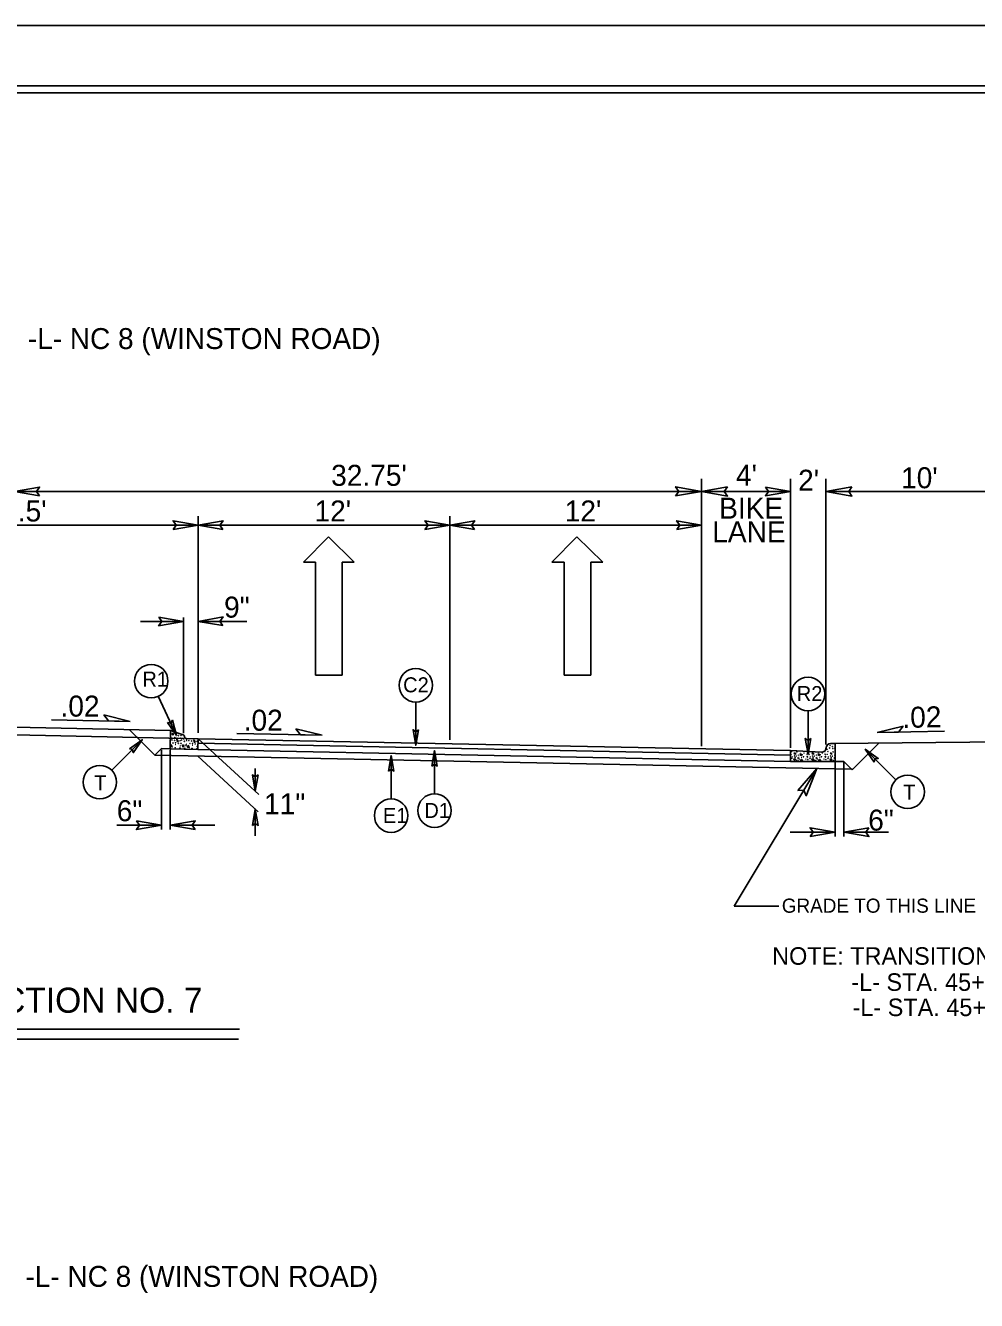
# Model space of a CAD drawing. Extents: x 957297 to 961629, y 830661 to 840840.
# Drawn here: x 959498.6 to 959851.8, y 836523.6 to 836997.1 of the extents above; entities that cross this region are included whole.
import ezdxf

# ---------------------------------------------------------------- set-up
doc = ezdxf.new("R2010")
doc.units = 0
for name, color, linetype in [('Default', 7, 'Continuous'), ('Old_Level_1', 7, 'Continuous'), ('Old_Level_11', 7, 'Continuous'), ('Old_Level_3', 7, 'Continuous'), ('Prop Dimension Text', 7, 'Continuous'), ('Prop Lane Arrow CELL', 7, 'Continuous'), ('Sheet Plot Border Inside CELL', 7, 'Continuous'), ('Sheet Plot Border Outside CELL', 7, 'Continuous'), ('Sheet Typical CELL', 7, 'Continuous'), ('Typical ID Circle CELL', 7, 'Continuous'), ('Typical Terminator CELL', 7, 'Continuous'), ('Typical Text ID Circle CELL', 7, 'Continuous')]:
    doc.layers.add(name, color=color, linetype=linetype)

# ---------------------------------------------------------------- blocks, each defined once
blk = doc.blocks.new('Lane Arrow Through')
at = {"layer": 'Prop Lane Arrow CELL'}
for p, q in [((-17.15, 1.6), (-3.15, 1.6)), ((-17.15, -1.7), (-17.15, 1.6)), ((-3.15, 1.6), (-3.15, 3.1)), ((-3.15, 3.1), (0, 0)), ((0, 0), (-3.15, -3.2)), ((-3.15, -1.7), (-17.15, -1.7)), ((-3.15, -3.2), (-3.15, -1.7))]:
    blk.add_line(p, q, dxfattribs=at)

msp = doc.modelspace()

# ---------------------------------------------------------------- linework, layer by layer
at = {"layer": 'Default'}
for p, q in [((959494.54, 836736.5), (959552.51, 836735.34)), ((959546.62, 836726.12), (959537.09, 836735.65)), ((959494.54, 836733.65), (959557.49, 836732.39))]:
    msp.add_line(p, q, dxfattribs=at)
at = {"layer": 'Old_Level_1'}
for p, q in [((959749.66, 836828.73), (959749.66, 836729.43)), ((959782.66, 836828.73), (959782.66, 836728.93)), ((959795.87, 836828.73), (959795.87, 836730.13)), ((959494.54, 836824.11), (959749.66, 836824.11)), ((959749.66, 836824.11), (959782.66, 836824.11)), ((959861.91, 836824.11), (959795.87, 836824.11)), ((959426.38, 836811.56), (959562.7, 836811.56)), ((959562.7, 836814.92), (959562.7, 836734.44)), ((959562.7, 836811.56), (959656.18, 836811.56)), ((959656.18, 836814.92), (959656.18, 836731.89)), ((959656.18, 836811.56), (959749.66, 836811.56)), ((959541.25, 836775.85), (959557.28, 836775.85)), ((959557.28, 836777.3), (959557.28, 836734.3)), ((959562.7, 836775.85), (959580.77, 836775.85)), ((959508.25, 836739.27), (959537.47, 836738.69)), ((959562.7, 836732.27), (959782.66, 836727.83)), ((959562.7, 836732.27), (959585.21, 836711.56)), ((959577.12, 836734.15), (959608.72, 836733.52)), ((959861.91, 836731.11), (959798.95, 836730.48)), ((959839.95, 836735.03), (959814.84, 836734.53)), ((959549.06, 836728.57), (959546.62, 836726.12)), ((959546.62, 836726.12), (959805.61, 836720.89)), ((959549.06, 836728.57), (959552.36, 836728.5)), ((959549.06, 836698.48), (959549.06, 836728.13)), ((959552.36, 836698.48), (959552.36, 836728.13)), ((959562.62, 836728.29), (959782.66, 836723.84)), ((959562.67, 836730.55), (959782.66, 836726.1)), ((959805.6, 836720.71), (959815.53, 836730.64)), ((959562.57, 836725.8), (959585.07, 836705.09)), ((959583.95, 836721.23), (959583.95, 836712.72)), ((959799.24, 836723.84), (959802.54, 836723.78)), ((959799.24, 836695.94), (959799.24, 836723.57)), ((959802.54, 836723.78), (959805.6, 836720.71)), ((959802.54, 836695.94), (959802.54, 836723.57)), ((959761.73, 836670.08), (959792.43, 836721.15)), ((959583.93, 836706.14), (959583.93, 836696.13)), ((959532.46, 836700.11), (959549.06, 836700.11)), ((959552.36, 836700.11), (959568.96, 836700.11)), ((959799.24, 836697.53), (959782.64, 836697.53)), ((959819.14, 836697.53), (959802.54, 836697.53)), ((959778.35, 836670.08), (959761.73, 836670.08)), ((959578.04, 836624.44), (959410.34, 836624.44)), ((959577.76, 836620.63), (959410.06, 836620.63))]:
    msp.add_line(p, q, dxfattribs=at)
at = {"layer": 'Old_Level_11'}
for p, q in [((959529.47, 836738.85), (959527.73, 836741.1)), ((959527.73, 836741.1), (959537.47, 836738.69)), ((959537.47, 836738.69), (959529.47, 836738.85)), ((959600.72, 836733.68), (959598.99, 836735.93)), ((959598.99, 836735.93), (959608.72, 836733.52)), ((959824.58, 836736.95), (959814.84, 836734.53)), ((959822.85, 836734.69), (959824.58, 836736.95)), ((959608.72, 836733.52), (959600.72, 836733.68)), ((959814.84, 836734.53), (959822.85, 836734.69))]:
    msp.add_line(p, q, dxfattribs=at)
for points in [[(959740.05, 836822.45), (959749.66, 836824.11), (959740, 836825.81), (959741.22, 836824.11)], [(959759.27, 836825.76), (959749.66, 836824.11), (959759.33, 836822.39), (959758.1, 836824.11)], [(959805.48, 836825.76), (959795.87, 836824.11), (959805.54, 836822.39), (959804.31, 836824.11)], [(959785.42, 836713.03), (959792.43, 836721.15), (959788.55, 836711.08), (959787.66, 836713.2)]]:
    msp.add_lwpolyline(points, close=True, dxfattribs=at)
at = {"layer": 'Old_Level_3'}
for p, q in [((959552.36, 836728.5), (959552.51, 836735.34)), ((959557.16, 836733.68), (959552.51, 836735.34)), ((959553.49, 836734.14), (959552.9, 836734.16)), ((959552.9, 836734.16), (959553.44, 836733.56)), ((959553.44, 836733.56), (959553.49, 836734.14)), ((959554.8, 836732.05), (959555.06, 836731.02)), ((959555.35, 836731.63), (959554.8, 836732.05)), ((959555.06, 836731.02), (959555.35, 836731.63)), ((959557.59, 836733.02), (959557.59, 836733.06)), ((959562.7, 836732.27), (959558.22, 836732.37)), ((959561.08, 836731.81), (959561.34, 836730.78)), ((959561.63, 836731.39), (959561.08, 836731.81)), ((959561.34, 836730.78), (959561.63, 836731.39)), ((959562.7, 836732.27), (959562.62, 836728.29)), ((959562.62, 836728.29), (959562.7, 836732.23)), ((959562.62, 836728.29), (959552.36, 836728.5)), ((959553, 836729.92), (959552.5, 836729.84)), ((959552.5, 836729.84), (959552.73, 836729.09)), ((959552.73, 836729.09), (959553, 836729.92)), ((959556.86, 836730.03), (959557.47, 836729.68)), ((959557.06, 836729.13), (959556.86, 836730.03)), ((959557.47, 836729.68), (959557.06, 836729.13)), ((959559.28, 836729.68), (959558.78, 836729.6)), ((959558.78, 836729.6), (959559.02, 836728.85)), ((959559.02, 836728.85), (959559.28, 836729.68)), ((959794.2, 836727.25), (959782.66, 836727.83)), ((959782.66, 836727.83), (959782.66, 836723.84)), ((959783.92, 836726.9), (959784.5, 836726.93)), ((959784.5, 836726.35), (959783.92, 836726.9)), ((959784.5, 836726.93), (959784.5, 836726.35)), ((959786.18, 836726.29), (959787.02, 836726.52)), ((959786.92, 836726.04), (959786.18, 836726.29)), ((959787.02, 836726.52), (959786.92, 836726.04)), ((959790.65, 836726.9), (959791.23, 836726.93)), ((959791.23, 836726.35), (959790.65, 836726.9)), ((959791.23, 836726.93), (959791.23, 836726.35)), ((959792.91, 836726.29), (959793.74, 836726.52)), ((959793.65, 836726.04), (959792.91, 836726.29)), ((959793.74, 836726.52), (959793.65, 836726.04)), ((959794.2, 836727.25), (959794.2, 836727.25)), ((959795.9, 836728.29), (959795.75, 836728.32)), ((959795.79, 836728.43), (959795.9, 836728.29)), ((959797.38, 836726.9), (959797.96, 836726.93)), ((959797.96, 836726.35), (959797.38, 836726.9)), ((959798.95, 836730.48), (959797.57, 836730.48)), ((959797.96, 836726.93), (959797.96, 836726.35)), ((959799.24, 836727.16), (959799.24, 836730.19)), ((959799.24, 836723.84), (959799.24, 836727.16)), ((959782.66, 836723.84), (959799.24, 836723.84)), ((959784.13, 836724.88), (959783.95, 836724.26)), ((959783.95, 836724.26), (959784.59, 836724.23)), ((959784.59, 836724.23), (959784.13, 836724.88)), ((959786.86, 836724.57), (959786.3, 836724.17)), ((959786.3, 836724.17), (959787.2, 836723.96)), ((959787.2, 836723.96), (959786.86, 836724.57)), ((959790.86, 836724.88), (959790.68, 836724.26)), ((959790.68, 836724.26), (959791.32, 836724.23)), ((959791.32, 836724.23), (959790.86, 836724.88)), ((959793.59, 836724.57), (959793.03, 836724.17)), ((959793.03, 836724.17), (959793.93, 836723.96)), ((959793.93, 836723.96), (959793.59, 836724.57)), ((959797.58, 836724.88), (959797.41, 836724.26)), ((959797.41, 836724.26), (959798.05, 836724.23)), ((959798.05, 836724.23), (959797.58, 836724.88))]:
    msp.add_line(p, q, dxfattribs=at)
for centre, radius in [((959552.96, 836732.52), 0.0434), ((959553.01, 836731.77), 0.0434), ((959553.38, 836730.69), 0.0434), ((959553.93, 836734.72), 0.0434), ((959554.02, 836731.66), 0.0434), ((959554.08, 836732.77), 0.0434), ((959554.31, 836730.76), 0.0434), ((959554.87, 836732.42), 0.0434), ((959555.39, 836733.39), 0.0434), ((959556, 836731.5), 0.0434), ((959556.17, 836732.42), 0.0434), ((959556.32, 836733.53), 0.0434), ((959556.62, 836731.79), 0.0434), ((959557.46, 836731.96), 0.0434), ((959557.6, 836731.28), 0.0434), ((959558.38, 836731.79), 0.0434), ((959558.49, 836731.58), 0.0434), ((959559.29, 836731.54), 0.0434), ((959560.3, 836731.42), 0.0434), ((959561.15, 836732.18), 0.0434), ((959562.28, 836731.26), 0.0434), ((959553.2, 836729.24), 0.0434), ((959554.18, 836728.94), 0.0434), ((959554.39, 836730.11), 0.0434), ((959555.33, 836730.52), 0.0434), ((959555.97, 836728.78), 0.0434), ((959556.08, 836729.61), 0.0434), ((959556.32, 836730.53), 0.0434), ((959557.64, 836728.71), 0.0434), ((959558.16, 836728.61), 0.0434), ((959558.18, 836729.66), 0.0434), ((959558.3, 836730.2), 0.0434), ((959559.48, 836729), 0.0434), ((959559.67, 836730.45), 0.0434), ((959560.46, 836728.7), 0.0434), ((959560.6, 836730.52), 0.0434), ((959560.67, 836729.87), 0.0434), ((959561.61, 836730.28), 0.0434), ((959562.25, 836728.54), 0.0434), ((959562.36, 836729.37), 0.0434), ((959562.6, 836730.29), 0.0434), ((959782.87, 836726.44), 0.0432), ((959783.15, 836727.55), 0.0432), ((959785.08, 836727.36), 0.0432), ((959785.63, 836726.16), 0.0432), ((959786.34, 836726.75), 0.0432), ((959787.78, 836726.9), 0.0432), ((959788.86, 836726.5), 0.0432), ((959789.6, 836726.44), 0.0432), ((959792.36, 836726.16), 0.0432), ((959793.07, 836726.75), 0.0432), ((959794.51, 836726.9), 0.0432), ((959795.5, 836727.51), 0.0432), ((959795.59, 836726.5), 0.0432), ((959796.26, 836728.35), 0.0432), ((959796.3, 836729.64), 0.0432), ((959796.33, 836726.44), 0.0432), ((959796.6, 836727.55), 0.0432), ((959797.25, 836728.84), 0.0432), ((959797.4, 836729.76), 0.0432), ((959798.26, 836729.39), 0.0432), ((959798.42, 836728.65), 0.0432), ((959798.54, 836727.36), 0.0432), ((959799.09, 836726.16), 0.0432), ((959799.18, 836728.75), 0.0432), ((959783.21, 836724.97), 0.0432), ((959783.36, 836725.52), 0.0432), ((959784.16, 836725.85), 0.0432), ((959784.41, 836725.31), 0.0432), ((959784.93, 836725.76), 0.0432), ((959785.08, 836724.23), 0.0432), ((959785.52, 836725.09), 0.0432), ((959785.6, 836723.98), 0.0432), ((959785.81, 836725.28), 0.0432), ((959785.91, 836724.75), 0.0432), ((959786.86, 836725.28), 0.0432), ((959787.51, 836725.55), 0.0432), ((959788.46, 836724.66), 0.0432), ((959788.89, 836725.7), 0.0432), ((959788.98, 836725.43), 0.0432), ((959789.14, 836724.51), 0.0432), ((959789.94, 836724.97), 0.0432), ((959790.09, 836725.52), 0.0432), ((959790.89, 836725.85), 0.0432), ((959791.14, 836725.31), 0.0432), ((959791.66, 836725.76), 0.0432), ((959791.81, 836724.23), 0.0432), ((959792.24, 836725.09), 0.0432), ((959792.33, 836723.98), 0.0432), ((959792.54, 836725.28), 0.0432), ((959792.63, 836724.75), 0.0432), ((959793.59, 836725.28), 0.0432), ((959794.23, 836725.55), 0.0432), ((959795.19, 836724.66), 0.0432), ((959795.62, 836725.7), 0.0432), ((959795.71, 836725.43), 0.0432), ((959795.86, 836724.51), 0.0432), ((959796.66, 836724.97), 0.0432), ((959796.82, 836725.52), 0.0432), ((959797.62, 836725.85), 0.0432), ((959797.86, 836725.31), 0.0432), ((959798.39, 836725.76), 0.0432), ((959798.54, 836724.23), 0.0432), ((959798.97, 836725.09), 0.0432), ((959799.06, 836723.98), 0.0432)]:
    msp.add_circle(centre, radius, dxfattribs=at)
for centre, radius, start, end in [((959556.95, 836733.07), 0.641, 358.794, 70.359), ((959558.23, 836733.01), 0.641, 178.794, 268.794), ((959552.6, 836728.54), 0.0434, 25.8325, 153.0355), ((959788.77, 836727.51), 0.0432, 164.1199, 10.1626), ((959791.81, 836727.36), 0.0432, 162.062, 12.2205), ((959794.28, 836728.89), 1.64, 267.1376, 358.9266), ((959797.58, 836728.82), 1.66, 90, 178.9266), ((959798.95, 836730.19), 0.287, 0, 90), ((959799.06, 836730.41), 0.0432, 169.6531, 280.3469), ((959799.27, 836725.28), 0.0432, 150.4173, 209.5827)]:
    msp.add_arc(centre, radius, start, end, dxfattribs=at)
at = {"layer": 'Sheet Plot Border Inside CELL'}
msp.add_lwpolyline([(960390.3, 836974.7), (958723.8, 836974.7), (958723.8, 835919.6), (960390.3, 835919.6)], close=True, dxfattribs=at)
at = {"layer": 'Sheet Plot Border Outside CELL'}
msp.add_lwpolyline([(960394.8, 836997.15), (958710.8, 836997.15), (958710.8, 835897.15), (960394.8, 835897.15)], close=True, dxfattribs=at)
at = {"layer": 'Sheet Typical CELL'}
msp.add_lwpolyline([(960377.8, 836972.15), (958877.8, 836972.15), (958877.8, 835922.15), (960377.8, 835922.15)], close=True, dxfattribs=at)
at = {"layer": 'Typical ID Circle CELL'}
for p, q in [((959547.93, 836748), (959554.72, 836733.42)), ((959643.55, 836745.9), (959643.55, 836729.81)), ((959789.22, 836742.65), (959789.22, 836726.56)), ((959530.59, 836720.51), (959541.98, 836731.89)), ((959634.38, 836709.93), (959634.38, 836726.02)), ((959650.51, 836711.79), (959650.51, 836727.88)), ((959821.83, 836716.94), (959810.46, 836728.32))]:
    msp.add_line(p, q, dxfattribs=at)
for centre in [(959545.29, 836753.64), (959643.55, 836752.12), (959789.22, 836748.87), (959526.2, 836716.11), (959826.23, 836712.54), (959650.51, 836705.57), (959634.38, 836703.7)]:
    msp.add_circle(centre, 6.23, dxfattribs=at)
at = {"layer": 'Typical Terminator CELL'}
for points in [[(959503.76, 836822.52), (959494.54, 836824.11), (959503.81, 836825.74), (959502.63, 836824.11)], [(959773.44, 836825.69), (959782.66, 836824.11), (959773.39, 836822.47), (959774.57, 836824.11)], [(959553.48, 836809.98), (959562.7, 836811.56), (959553.43, 836813.2), (959554.61, 836811.56)], [(959571.92, 836809.98), (959562.7, 836811.56), (959571.98, 836813.2), (959570.8, 836811.56)], [(959646.96, 836809.98), (959656.18, 836811.56), (959646.91, 836813.2), (959648.09, 836811.56)], [(959665.4, 836809.98), (959656.18, 836811.56), (959665.46, 836813.2), (959664.28, 836811.56)], [(959740.44, 836809.98), (959749.66, 836811.56), (959740.39, 836813.2), (959741.57, 836811.56)], [(959548.06, 836777.44), (959557.28, 836775.85), (959548, 836774.21), (959549.18, 836775.85)], [(959571.92, 836774.26), (959562.7, 836775.85), (959571.98, 836777.49), (959570.8, 836775.85)], [(959551.39, 836738.22), (959554.72, 836733.42), (959553.2, 836739.1), (959552.59, 836738)], [(959644.54, 836735.57), (959643.55, 836729.81), (959642.52, 836735.61), (959643.55, 836734.87)], [(959537.2, 836728.52), (959541.98, 836731.89), (959538.6, 836727.07), (959538.4, 836728.31)], [(959790.22, 836732.32), (959789.22, 836726.56), (959788.2, 836732.35), (959789.22, 836731.62)], [(959633.39, 836720.25), (959634.38, 836726.02), (959635.4, 836720.22), (959634.38, 836720.96)], [(959649.52, 836722.11), (959650.51, 836727.88), (959651.54, 836722.08), (959650.51, 836722.82)], [(959813.83, 836723.54), (959810.46, 836728.32), (959815.28, 836724.94), (959814.03, 836724.74)], [(959584.99, 836718.79), (959583.95, 836712.72), (959582.87, 836718.83), (959583.95, 836718.05)], [(959582.89, 836700.07), (959583.93, 836706.14), (959585.01, 836700.04), (959583.93, 836700.81)], [(959539.84, 836701.7), (959549.06, 836700.11), (959539.79, 836698.48), (959540.97, 836700.11)], [(959561.59, 836698.53), (959552.36, 836700.11), (959561.64, 836701.75), (959560.46, 836700.11)], [(959790.01, 836695.94), (959799.24, 836697.53), (959789.96, 836699.17), (959791.14, 836697.53)], [(959811.76, 836699.12), (959802.54, 836697.53), (959811.81, 836695.89), (959810.63, 836697.53)]]:
    msp.add_lwpolyline(points, close=True, dxfattribs=at)

# ---------------------------------------------------------------- block references
at = {"layer": 'Old_Level_1', "xscale": 3, "yscale": 3, "rotation": 90}
for p in [(959611.11, 836807.26), (959703.41, 836807.26)]:
    msp.add_blockref('Lane Arrow Through', p, dxfattribs=at)

# ---------------------------------------------------------------- texts
at = {"layer": 'Old_Level_1'}
for s, height, p in [('GRADE TO THIS LINE', 5.2473, (959779.48, 836667.63)), ('NOTE: TRANSITION FROM T.S. NO. 7 TO T.S. NO. 8 -L- STA. 45+90.00 TO STA. 50+50.00', 6.5088, (959775.89, 836648.31)), ("-L- STA. 45+90.00 TO STA. 50+50.00 (OUTSIDE LANE TRANSITION 16' TO 0') LT./RT.", 6.5088, (959805.29, 836638.62)), ('TYPICAL SECTION NO. 7', 9.3239, (959417.46, 836630.48)), ("-L- STA. 45+90.00 TO STA. 50+50.00 (MEDIAN TRANSITION 17.5' TO 12')", 6.5088, (959805.75, 836629.24))]:
    msp.add_text(s, height=height, dxfattribs=at).set_placement(p)
at = {"layer": 'Old_Level_3'}
for s, p in [("4'", (959762.46, 836826.24)), ("2'", (959785.53, 836824.35)), ("10'", (959823.77, 836825.28)), ('BIKE', (959756.22, 836813.99)), ('LANE', (959753.64, 836805.24))]:
    msp.add_text(s, height=7.801, dxfattribs=at).set_placement(p)
at = {"layer": 'Prop Dimension Text'}
for s, height, rotation, p in [('-L- NC 8 (WINSTON ROAD)', 7.7675, 0, (959499.5, 836876.99)), ("32.75'", 7.801, 0, (959612.12, 836826.18)), ("17.5'", 7.801, 0, (959484.14, 836812.94)), ("12'", 7.801, 0, (959605.92, 836812.94)), ("12'", 7.801, 0, (959698.86, 836812.94)), ('9"', 7.801, 0, (959572.35, 836777.23)), ('.02', 7.801, 360, (959511.61, 836740.47)), ('.02', 7.801, 360, (959579.63, 836735.23)), ('.02', 7.801, 1.1839, (959824.33, 836736.23)), ('11"', 7.801, 0, (959587.2, 836704.2)), ('6"', 7.801, 0, (959532.5, 836701.61)), ('6"', 7.801, 0, (959811.56, 836698.13)), ('-L- NC 8 (WINSTON ROAD)', 7.7675, 0, (959498.62, 836528.68))]:
    msp.add_text(s, height=height, rotation=rotation, dxfattribs=at).set_placement(p)
at = {"layer": 'Typical Text ID Circle CELL'}
for s, height, p in [('R1', 5.572, (959542, 836751.6)), ('C2', 5.572, (959638.84, 836749.49)), ('R2', 5.572, (959785.03, 836746.24)), ('T', 5.57, (959524.13, 836713.1)), ('T', 5.57, (959824.53, 836709.56)), ('D1', 5.572, (959646.72, 836702.83)), ('E1', 5.572, (959631.35, 836700.96))]:
    msp.add_text(s, height=height, dxfattribs=at).set_placement(p)

doc.saveas('drawing.dxf')
